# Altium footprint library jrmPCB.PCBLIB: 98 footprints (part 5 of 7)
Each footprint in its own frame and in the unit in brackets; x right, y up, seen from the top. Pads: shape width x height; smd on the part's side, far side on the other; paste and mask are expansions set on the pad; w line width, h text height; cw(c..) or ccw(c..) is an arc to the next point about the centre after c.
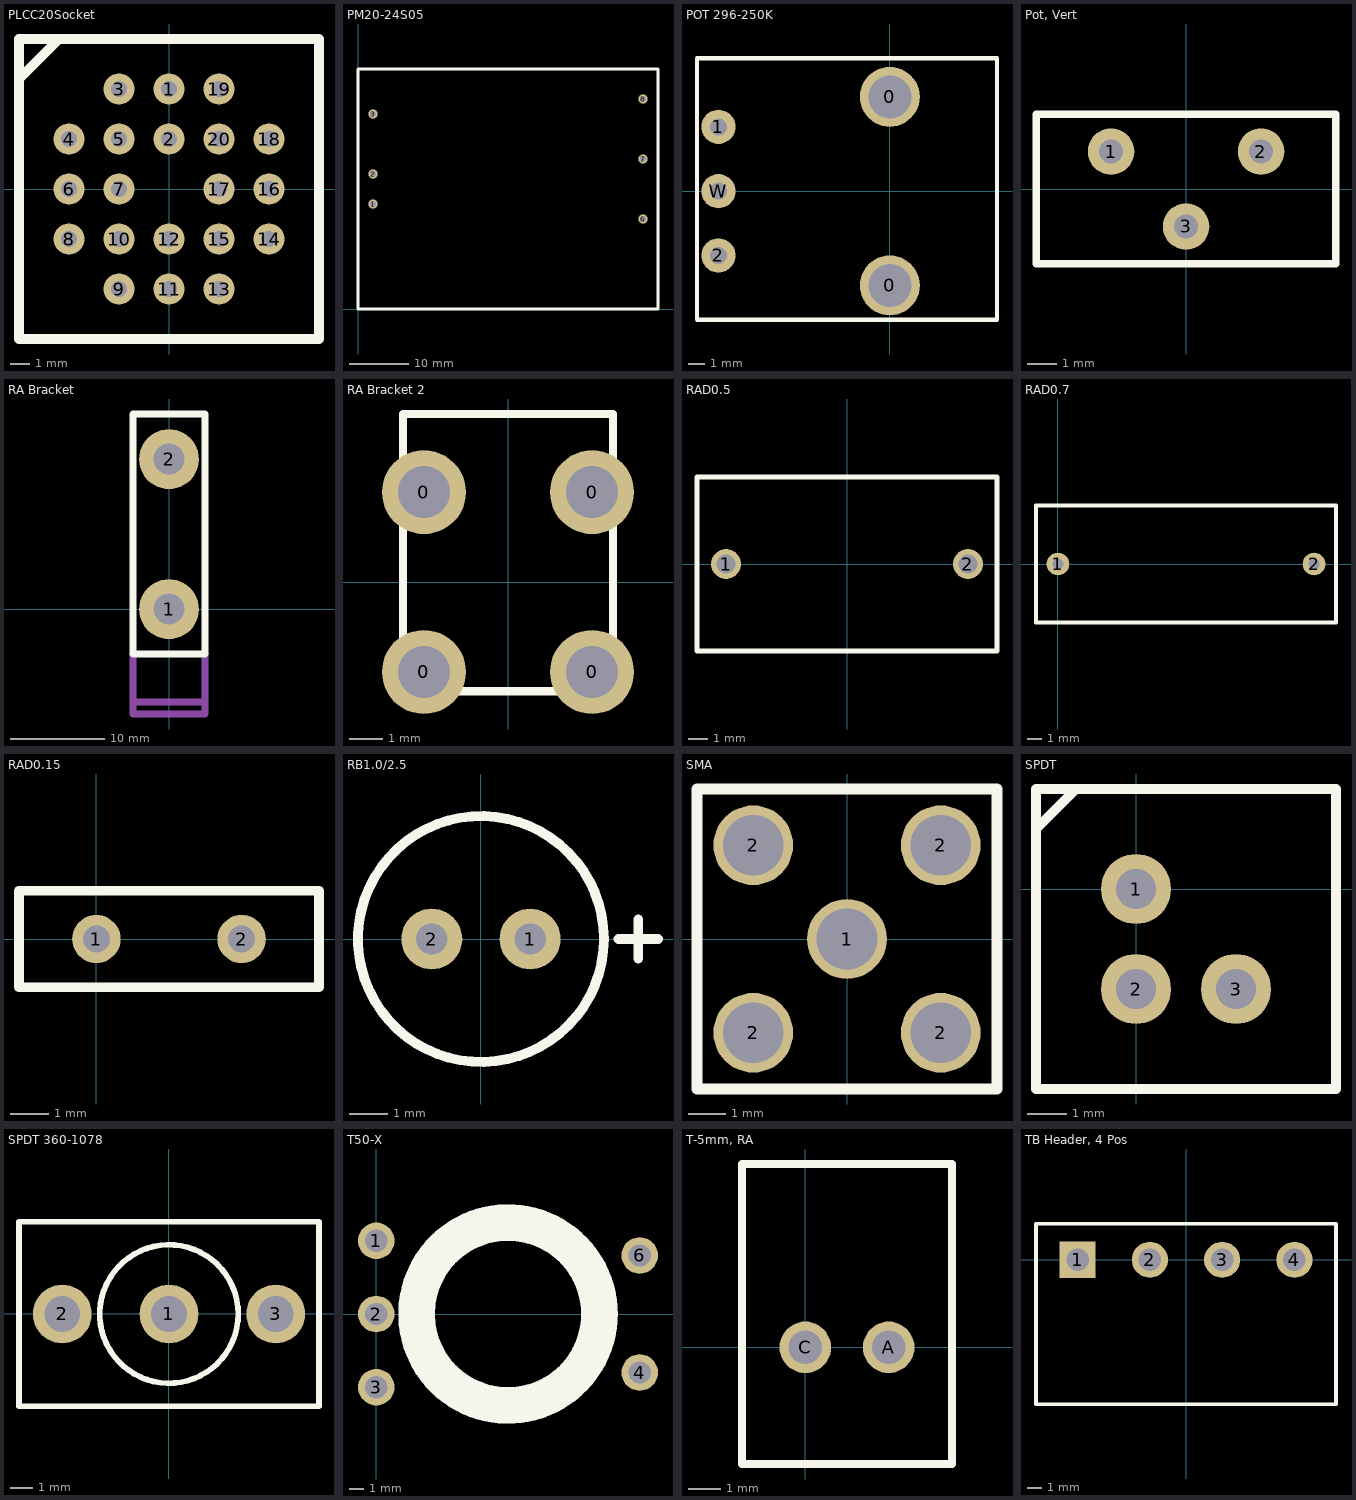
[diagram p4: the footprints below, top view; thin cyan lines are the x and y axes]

## PLCC20Socket [mil]
pads (20):
  round 62 hole 32: 1(0,200) 2(0,100) 3(-100,200) 4(-200,100) 5(-100,100) 6(-200,0) 7(-100,0) 8(-200,-100) 9(-100,-200) 10(-100,-100) 11(0,-200) 12(0,-100) 13(100,-200) 14(200,-100) 15(100,-100) 16(200,0) 17(100,0) 18(200,100) 19(100,200) 20(100,100)
Top Overlay:
  lines w20: -300,220 -220,300 ; -300,-300 300,-300 300,300 -300,300 -300,-300

## PM20-24S05 [mil]
pads (6):
  round 62 hole 40: 1(100,700) 2(100,900) 3(100,1300) 6(1900,600) 7(1900,1000) 8(1900,1400)
Top Overlay:
  lines w20: 0,0 0,1600 2000,1600 2000,0 0,0

## POT 296-250K [mil]
pads (5):
  round 140 hole 100: 0(0,-220) 0(0,220)
  round 80 hole 40: 1(-400,150) 2(-400,-150) W(-400,0)
Top Overlay:
  lines w10: -450,-300 -450,-110 -450,90 -450,310 250,310 250,110 250,-90 250,-300 -450,-300

## Pot, Vert [mil]
pads (3):
  round 62 hole 32: 1(-100,50) 2(100,50) 3(0,-50)
Top Overlay:
  lines w10: -200,-100 200,-100 200,100 -200,100 -200,-100

## RA Bracket [mil]
pads (2):
  round 250 hole 130: 1(0,0) 2(0,625)
Top Overlay:
  lines w30: -150,-187 -150,813 150,813 150,-187 -150,-187
Mechanical 2:
  lines w30: -150,-387 150,-387 ; -150,-187 -150,-437 150,-437 150,-187

## RA Bracket 2 [mil]
pads (4):
  round 100 hole 62: 0(-100,-107) 0(-100,107) 0(100,-107) 0(100,107)
Top Overlay:
  lines w10: -125,-130 -125,200 125,200 125,-130 -125,-130

## RAD0.5 [mil]
pads (2):
  round 62 hole 40: 1(-250,0) 2(250,0)
Top Overlay:
  lines w10: -310,160 -310,180 ; -310,180 -310,-180 310,-180 310,180 -310,180

## RAD0.7 [mil]
pads (2):
  round 62 hole 31: 1(0,0) 2(700,0)
Top Overlay:
  lines w10: -60,-160 0,-160 700,-160 760,-160 760,160 700,160 0,160 -60,160 -60,-160

## RAD0.15 [mil]
pads (2):
  round 50 hole 28: 1(0,0) 2(150,0)
Top Overlay:
  lines w10: 0,-50 150,-50 ; 0,50 150,50 ; 20,-50 -80,-50 -80,50 20,50 ; 130,-50 230,-50 230,50 130,50

## RB1.0/2.5 [mil]
pads (2):
  round 62 hole 32: 1(50,0) 2(-50,0)
Top Overlay:
  circle w10: c0,0 r125
  lines w10: 140,0 180,0 ; 160,-20 160,20

## SMA [mil]
pads (5):
  round 85 hole 65: 1(0,0) 2(-100,-100) 2(-100,100) 2(100,-100) 2(100,100)
Top Overlay:
  lines w12: -160,-160 160,-160 160,160 -160,160 -160,0 -160,-160

## SPDT [mil]
pads (3):
  round 70 hole 40: 1(0,0) 2(0,-100) 3(100,-100)
Top Overlay:
  lines w10: -100,60 -60,100 ; -100,-200 -100,100 200,100 200,-200 -100,-200

## SPDT 360-1078 [mil]
pads (3):
  round 102 hole 62: 1(0,0) 2(-185,0) 3(185,0)
Top Overlay:
  circle w10: c0,0 r120
  lines w10: -260,-160 -260,160 -20,160 165,160 260,160 260,-160 185,-160 0,-160 -260,-160

## T50-X [mil]
pads (5):
  round 100 hole 61: 1(0,200) 2(0,0) 3(0,-200) 4(720,-160) 6(720,160)
Top Overlay:
  circle w100: c360,0 r250

## T-5mm, RA [mil]
pads (2):
  round 62 hole 40: A(100,0) C(0,0)
Top Overlay:
  lines w10: -76,-140 176,-140 176,220 -76,220 -76,-140

## TB Header, 4 Pos [mil]
pads (4):
  rect 100x100 hole 62: 1(-300,0)
  round 100 hole 62: 2(-100,0) 3(100,0) 4(300,0)
Top Overlay:
  lines w10: -415,-400 -415,100 415,100 415,-400 -415,-400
